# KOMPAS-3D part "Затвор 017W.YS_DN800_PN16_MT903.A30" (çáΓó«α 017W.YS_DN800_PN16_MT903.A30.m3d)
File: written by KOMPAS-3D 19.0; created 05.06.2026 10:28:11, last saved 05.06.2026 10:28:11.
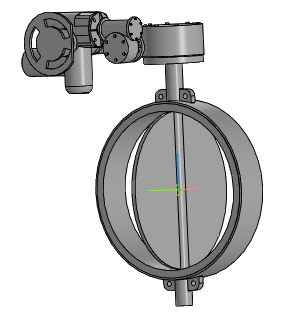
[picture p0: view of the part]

Document properties: Автор: Энергия; Полное имя файла: ..\..\..\3d для проектировщиков\x.x Тип 017W.Y(S) Затвор дисковый поворотный межфланцевый\Затвор 017W.Y(S)_DN32-DN1200_QT.A_MT903.A\Затвор 017W.YS_DN800_PN16_MT903.A30.a3d

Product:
- Part/product: Затвор 017W.YS_DN800_PN16_MT903.A30
    Масса: 623.743

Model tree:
1. Операция без истории:1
